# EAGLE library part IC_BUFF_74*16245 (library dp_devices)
16-bit BUS TRANSCEIVER, 3-state
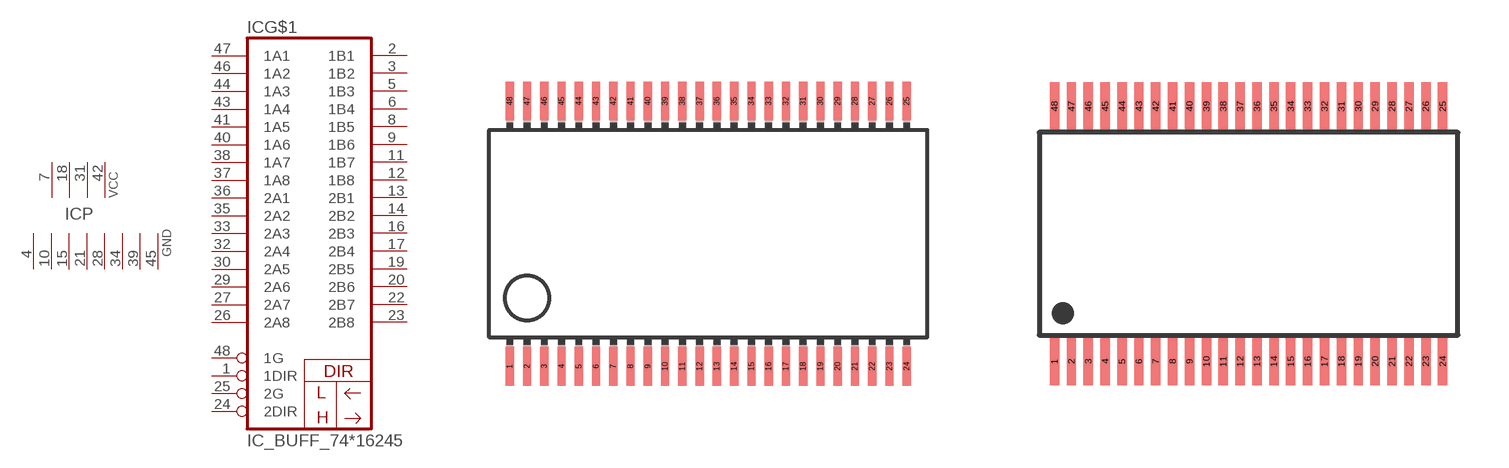
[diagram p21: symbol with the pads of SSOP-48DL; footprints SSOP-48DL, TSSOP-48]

Designator prefix IC; gates G$1=7416245 P=4PWR8GND

## IC_BUFF_7416245  [SSOP-48DL]
1  G$1:1DIR  in
2  G$1:1B1
3  G$1:1B2
4  P:GND  pwr
5  G$1:1B3
6  G$1:1B4
7  P:VCC  pwr
8  G$1:1B5
9  G$1:1B6
10  P:GND  pwr
11  G$1:1B7
12  G$1:1B8
13  G$1:2B1
14  G$1:2B2
15  P:GND  pwr
16  G$1:2B3
17  G$1:2B4
18  P:VCC  pwr
19  G$1:2B5
20  G$1:2B6
21  P:GND  pwr
22  G$1:2B7
23  G$1:2B8
24  G$1:2DIR  in
25  G$1:2G  in
26  G$1:2A8
27  G$1:2A7
28  P:GND  pwr
29  G$1:2A6
30  G$1:2A5
31  P:VCC  pwr
32  G$1:2A4
33  G$1:2A3
34  P:GND  pwr
35  G$1:2A2
36  G$1:2A1
37  G$1:1A8
38  G$1:1A7
39  P:GND  pwr
40  G$1:1A6
41  G$1:1A5
42  P:VCC  pwr
43  G$1:1A4
44  G$1:1A3
45  P:GND  pwr
46  G$1:1A2
47  G$1:1A1
48  G$1:1G  in

## IC_BUFF_7416245TSSOP48  [TSSOP-48]
Pads as for SSOP-48DL

## Footprint SSOP-48DL (pad centres in mm)
Shrink Small Outline Package
smd 0.305 x 1.422: 1 -6.985,-4.877; 2 -6.35,-4.877; 3 -5.715,-4.877; 4 -5.08,-4.877; 5 -4.445,-4.877; 6 -3.81,-4.877; 7 -3.175,-4.877; 8 -2.54,-4.877; 9 -1.905,-4.877; 10 -1.27,-4.877; 11 -0.635,-4.877; 12 0,-4.877; 13 0.635,-4.877; 14 1.27,-4.877; 15 1.905,-4.877; 16 2.54,-4.877; 17 3.175,-4.877; 18 3.81,-4.877; 19 4.445,-4.877; 20 5.08,-4.877; 21 5.715,-4.877; 22 6.35,-4.877; 23 6.985,-4.877; 24 7.62,-4.877; 25 7.62,4.877; 26 6.985,4.877; 27 6.35,4.877; 28 5.715,4.877; 29 5.08,4.877; 30 4.445,4.877; 31 3.81,4.877; 32 3.175,4.877; 33 2.54,4.877; 34 1.905,4.877; 35 1.27,4.877; 36 0.635,4.877; 37 0,4.877; 38 -0.635,4.877; 39 -1.27,4.877; 40 -1.905,4.877; 41 -2.54,4.877; 42 -3.175,4.877; 43 -3.81,4.877; 44 -4.445,4.877; 45 -5.08,4.877; 46 -5.715,4.877; 47 -6.35,4.877; 48 -6.985,4.877

## Footprint TSSOP-48 (pad centres in mm)
smd 0.28 x 1.43: 1 -5.49,-3.794; 2 -4.99,-3.794; 3 -4.49,-3.794; 4 -3.99,-3.794; 5 -3.49,-3.794; 6 -2.99,-3.794; 7 -2.49,-3.794; 8 -1.99,-3.794; 9 -1.49,-3.794; 10 -0.99,-3.794; 11 -0.49,-3.794; 12 0.01,-3.794; 13 0.51,-3.794; 14 1.01,-3.794; 15 1.51,-3.794; 16 2.01,-3.794; 17 2.51,-3.794; 18 3.01,-3.794; 19 3.51,-3.794; 20 4.01,-3.794; 21 4.51,-3.794; 22 5.01,-3.794; 23 5.51,-3.794; 24 6.01,-3.794; 25 6.01,3.756; 26 5.51,3.756; 27 5.01,3.756; 28 4.51,3.756; 29 4.01,3.756; 30 3.51,3.756; 31 3.01,3.756; 32 2.51,3.756; 33 2.01,3.756; 34 1.51,3.756; 35 1.01,3.756; 36 0.51,3.756; 37 0.01,3.756; 38 -0.49,3.756; 39 -0.99,3.756; 40 -1.49,3.756; 41 -1.99,3.756; 42 -2.49,3.756; 43 -2.99,3.756; 44 -3.49,3.756; 45 -3.99,3.756; 46 -4.49,3.756; 47 -4.99,3.756; 48 -5.49,3.756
